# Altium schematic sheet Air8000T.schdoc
size 601 x 429 mm; Symbol: Drawing-Symbol_A2; Device: Drawing-Symbol_A2; Company: 嘉立创EDA; Version: V1.0; Page Size: A2; @Project Name: 8000; @Page Count: 1; @Update Date: 2025-03-21; @Create Date: 2025-03-21; @Schematic Name: Schematic1; @Page No: 1; @Page Name: P1; @Create Time: 08:01:54; @Update Time: 16:01:54; Width: 2338; Height: 1652; Region Start: 1; X Region Count: 6; Y Region Count: 4; Blade Width: 10; Title Block Position: 3; @Board Name: PCB7
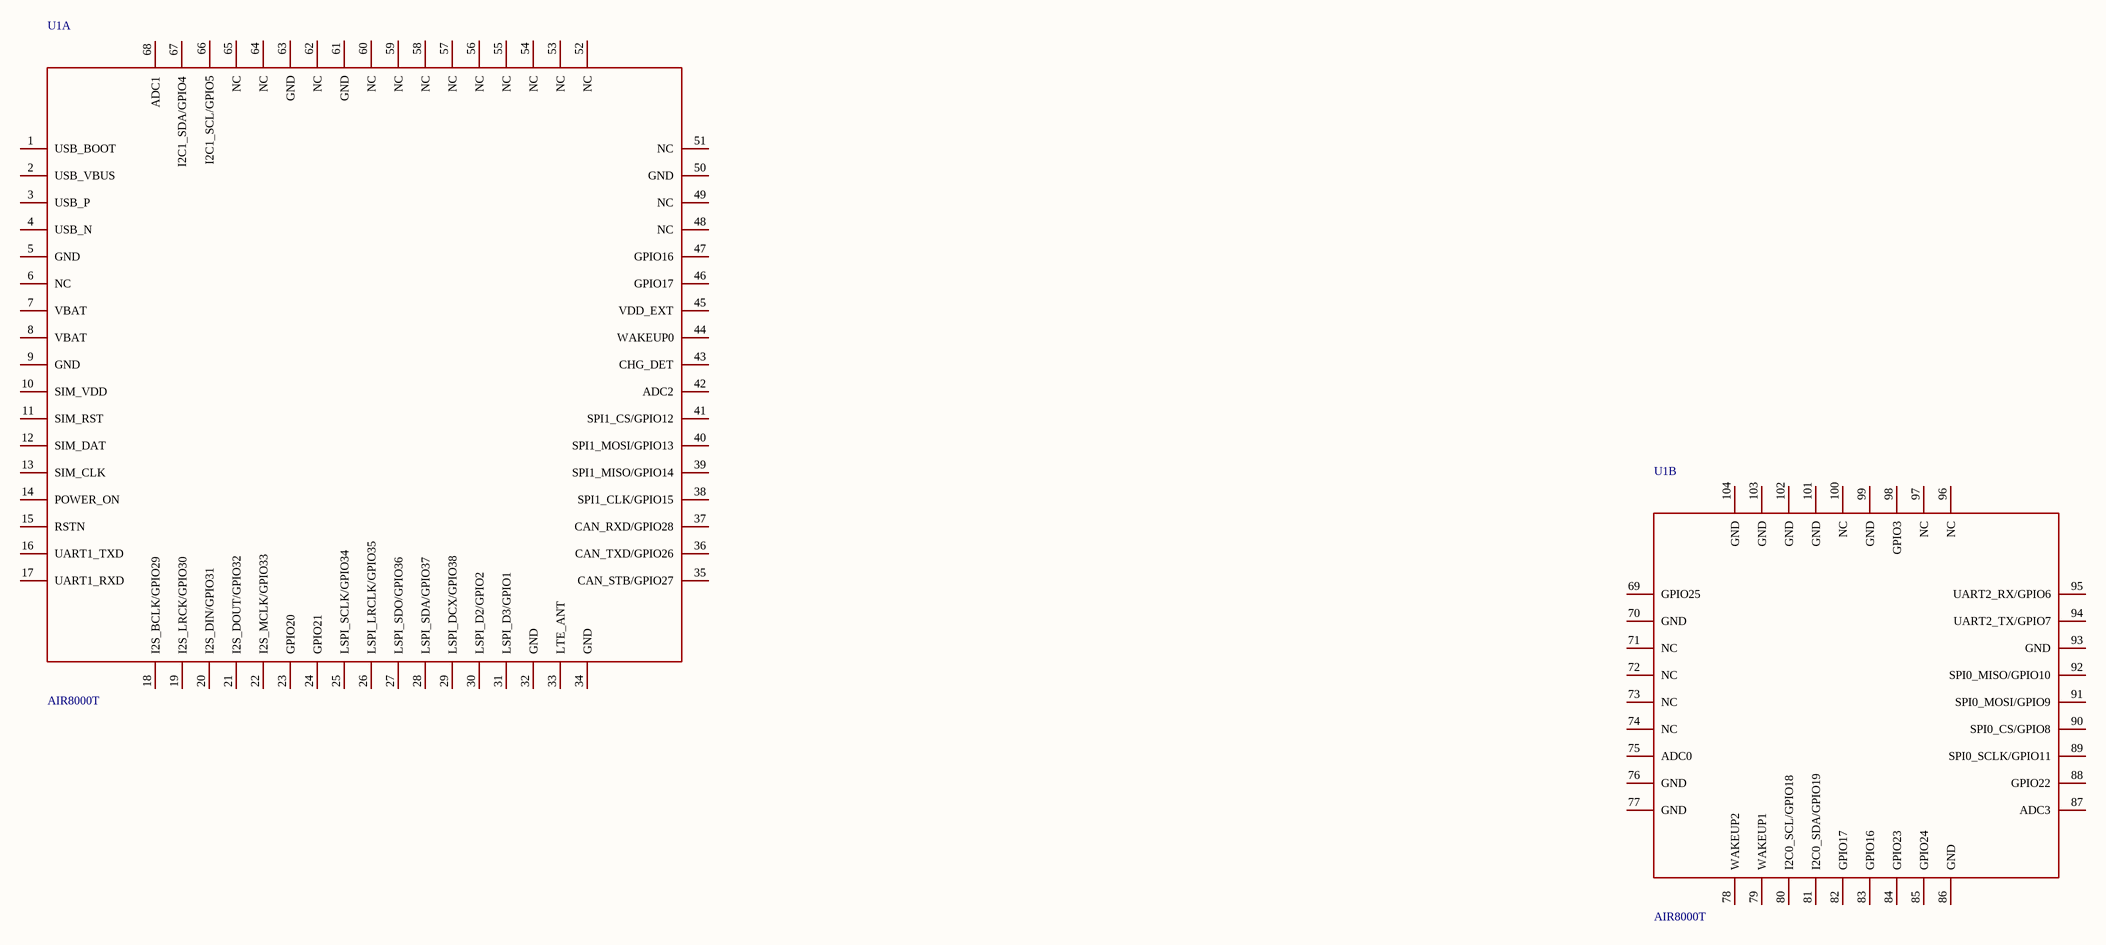
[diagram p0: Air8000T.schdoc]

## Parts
U1  AIR8000T  [AIR8000T-PADS]  (parts A,B of 2)

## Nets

Not connected (* = marked no-connect by the designer): U1 1(USB_BOOT) 2(USB_VBUS) 3(USB_P) 4(USB_N) 5(GND) 6(NC) 7(VBAT) 8(VBAT) 9(GND) 10(SIM_VDD) 11(SIM_RST) 12(SIM_DAT) 13(SIM_CLK) 14(POWER_ON) 15(RSTN) 16(UART1_TXD) 17(UART1_RXD) 18(I2S_BCLK/GPIO29) 19(I2S_LRCK/GPIO30) 20(I2S_DIN/GPIO31) 21(I2S_DOUT/GPIO32) 22(I2S_MCLK/GPIO33) 23(GPIO20) 24(GPIO21) 25(LSPI_SCLK/GPIO34) 26(LSPI_LRCLK/GPIO35) 27(LSPI_SDO/GPIO36) 28(LSPI_SDA/GPIO37) 29(LSPI_DCX/GPIO38) 30(LSPI_D2/GPIO2) 31(LSPI_D3/GPIO1) 32(GND) 33(LTE_ANT) 34(GND) 35(CAN_STB/GPIO27) 36(CAN_TXD/GPIO26) 37(CAN_RXD/GPIO28) 38(SPI1_CLK/GPIO15) 39(SPI1_MISO/GPIO14) 40(SPI1_MOSI/GPIO13) 41(SPI1_CS/GPIO12) 42(ADC2) 43(CHG_DET) 44(WAKEUP0) 45(VDD_EXT) 46(GPIO17) 47(GPIO16) 48(NC) 49(NC) 50(GND) 51(NC) 52(NC) 53(NC) 54(NC) 55(NC) 56(NC) 57(NC) 58(NC) 59(NC) 60(NC) 61(GND) 62(NC) 63(GND) 64(NC) 65(NC) 66(I2C1_SCL/GPIO5) 67(I2C1_SDA/GPIO4) 68(ADC1) 69(GPIO25) 70(GND) 71(NC) 72(NC) 73(NC) 74(NC) 75(ADC0) 76(GND) 77(GND) 78(WAKEUP2) 79(WAKEUP1) 80(I2C0_SCL/GPIO18) 81(I2C0_SDA/GPIO19) 82(GPIO17) 83(GPIO16) 84(GPIO23) 85(GPIO24) 86(GND) 87(ADC3) 88(GPIO22) 89(SPI0_SCLK/GPIO11) 90(SPI0_CS/GPIO8) 91(SPI0_MOSI/GPIO9) 92(SPI0_MISO/GPIO10) 93(GND) 94(UART2_TX/GPIO7) 95(UART2_RX/GPIO6) 96(NC) 97(NC) 98(GPIO3) 99(GND) 100(NC) 101(GND) 102(GND) 103(GND) 104(GND)

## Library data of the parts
U1 = AIR8000T: Add into BOM: yes; Relevance: []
